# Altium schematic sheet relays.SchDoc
size A4
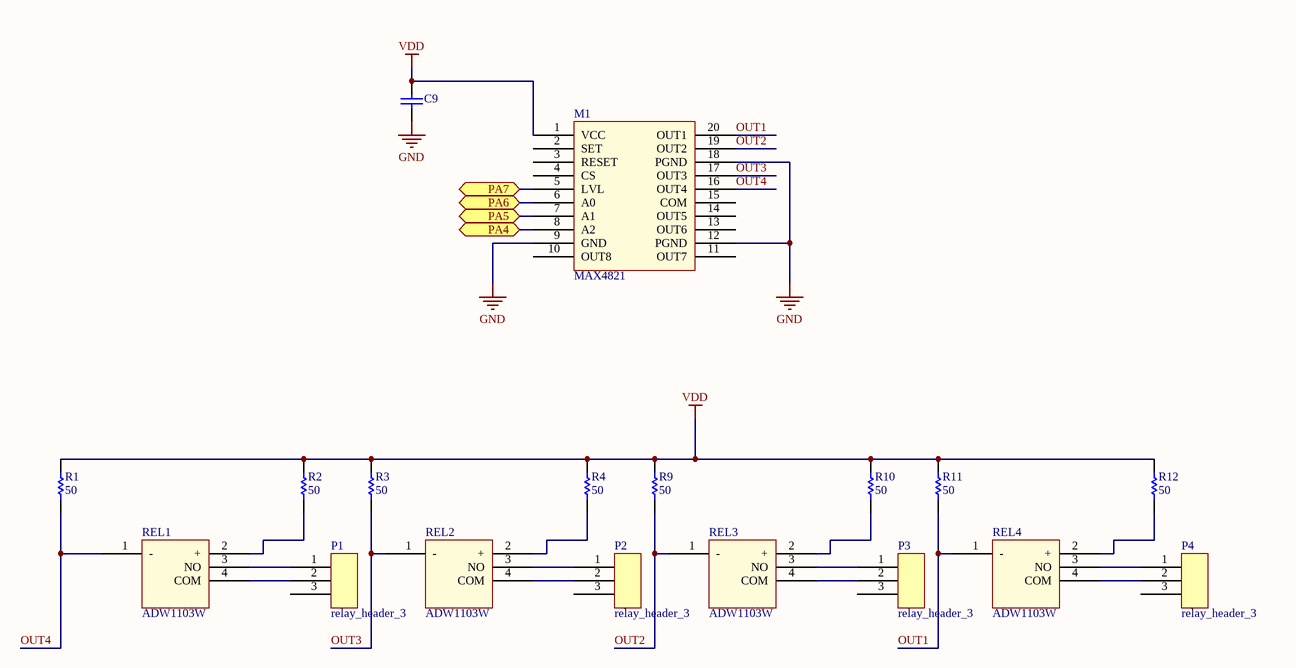
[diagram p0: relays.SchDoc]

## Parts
C9  Cap Semi  [1608[0603]]  (value not drawn)
M1  MAX4821  [MAX4821]
P1  relay_header_3  [ac_header_3]
P2  relay_header_3  [ac_header_3]
P3  relay_header_3  [ac_header_3]
P4  relay_header_3  [ac_header_3]
R1  50  [0603R]
R2  50  [0603R]
R3  50  [0603R]
R4  50  [0603R]
R9  50  [0603R]
R10  50  [0603R]
R11  50  [0603R]
R12  50  [0603R]
REL1  ADW1103W  [ADW1103W]
REL2  ADW1103W  [ADW1103W]
REL3  ADW1103W  [ADW1103W]
REL4  ADW1103W  [ADW1103W]

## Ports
PA4, PA5, PA6, PA7

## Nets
GND: C9.2 M1.9(GND) M1.12(PGND) M1.18(PGND)
VDD: C9.1 M1.1(VCC) R1.1 R2.1 R3.1 R4.1 R9.1 R10.1 R11.1 R12.1
OUT1: M1.20(OUT1) R11.2 REL4.1(-)
OUT2: M1.19(OUT2) R9.2 REL3.1(-)
OUT3: M1.17(OUT3) R3.2 REL2.1(-)
OUT4: M1.16(OUT4) R1.2 REL1.1(-)
PA4: M1.8(A2) ; port PA4
PA5: M1.7(A1) ; port PA5
PA6: M1.6(A0) ; port PA6
PA7: M1.5(LVL) ; port PA7
NetP1_1: P1.1 REL1.3(NO)
NetP1_2: P1.2 REL1.4(COM)
NetP2_1: P2.1 REL2.3(NO)
NetP2_2: P2.2 REL2.4(COM)
NetP3_1: P3.1 REL3.3(NO)
NetP3_2: P3.2 REL3.4(COM)
NetP4_1: P4.1 REL4.3(NO)
NetP4_2: P4.2 REL4.4(COM)
NetR2_2: R2.2 REL1.2(+)
NetR4_2: R4.2 REL2.2(+)
NetR10_2: R10.2 REL3.2(+)
NetR12_2: R12.2 REL4.2(+)

Not connected (* = marked no-connect by the designer): M1 2(SET) 3(RESET) 4(CS) 10(OUT8) 11(OUT7) 13(OUT6) 14(OUT5) 15(COM); P1 3; P2 3; P3 3; P4 3

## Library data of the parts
C9 = Cap Semi: Capacitor (Semiconductor SIM Model); Manufacturer: TDK; ProductNumber: C1608X5R1H104K080AA; Vendor Name: Digikey
M1 = MAX4821: Manufacturer: Maxim Integrated; ProductNumber: MAX4821EUP+; Vendor Name: Digikey; Vendor PN: MAX4821EUP+-ND
P1 = relay_header_3: Manufacturer: On Shore Technology; ProductNumber: OSTTC032162; Vendor Name: Digikey; Vendor PN: ED2610-ND
P2-P4 = relay_header_3: Manufacturer: On Shore Technology; ProductNumber: OSTTC032162; Vendor Name: Digikey
R1 = Res1: Resistor; Manufacturer: Vishay Dale; Value: 50 Ohms; ProductNumber: CRCW060350R0FKEA; Vendor Name: Farnell; Vendor PN: 2112878
R2-R4 R9-R12 = Res1: Resistor; Manufacturer: Vishay Dale; ProductNumber: CRCW060350R0FKEA; Vendor Name: Digikey
REL1 = ADW1103W: Manufacturer: Panasonic; Vendor Name: Mouser; Vendor PN: 769-ADW1103TW
REL2-REL4 = ADW1103W: Manufacturer: Panasonic; Vendor Name: Digikey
